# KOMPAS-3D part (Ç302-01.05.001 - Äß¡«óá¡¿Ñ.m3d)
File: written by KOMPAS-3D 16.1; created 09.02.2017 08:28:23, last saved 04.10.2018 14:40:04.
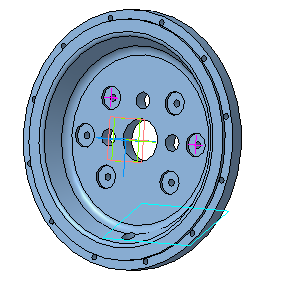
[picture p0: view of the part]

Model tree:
1. Эскиз:24
2. Операция вращения:2
     Угол 1 = 360
3. Эскиз:25
4. Отверстие:1
     Глубина выреза = 40; Диаметр отверстия = 8.5; Угол конуса торца = 118; Координата X = 45.9619; Координата Y = 45.9619; Диаметр цековки = 28; Глубина цековки = 4
5. Массив по концентрической сетке:1  (with: Отверстие:1, Эскиз:25)  (4 pattern instances)
     Геометрический массив = 3; Шаг 2 = 360
6. Эскиз:26
7. Вырезать элемент выдавливания:1
     Расстояние 1 = 40.5
8. Массив по концентрической сетке:2  (with: Вырезать элемент выдавливания:1, Эскиз:26)  (12 pattern instances)
     Геометрический массив = 11; Шаг 2 = 360
9. Фаска:1
     Угол = 45; Длина 1 = 0.5; Длина 2 = 0.5
10. Скругление:1
     Радиус = 12
11. Касательная плоскость:1
12. Эскиз:27
13. Вырезать элемент выдавливания:2
     Расстояние 1 = 72.4422
14. Эскиз:28
15. Отверстие:2
     Глубина выреза = 40; Диаметр отверстия = 8.5; Угол конуса торца = 118; Координата Y = -80; Диаметр цековки = 28; Глубина цековки = 4
16. Зеркальный массив:1
17. Экземпляр ( 1 )
18. Экземпляр ( 2 )  (with: Отверстие:2)
19. Эскиз:29
20. Вырезать элемент выдавливания:3
     Расстояние 1 = 16.5
21. Массив по концентрической сетке:3  (with: Вырезать элемент выдавливания:3, Эскиз:29)  (3 pattern instances)
     Геометрический массив = 2; Шаг 2 = 180
22. Эскиз:30
23. Вырезать элемент выдавливания:4  (labels: А302-01.05.001)
     Толщина стенки 1 = 0.1; Расстояние 2 = 28; Расстояние 1 = 16.5

Expressions: 250/2-3; 19.5+5.5+3
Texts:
  Линейный размер с обрывом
